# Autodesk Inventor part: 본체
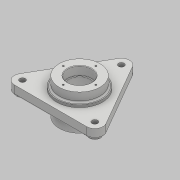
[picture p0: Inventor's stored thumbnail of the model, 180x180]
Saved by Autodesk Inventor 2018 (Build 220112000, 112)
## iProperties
Created: 2023-04
Part Number: 본체
Material: 일반
Document SubType Name: Modeling
Designer: home
Density: 1 g/cm^3
Appearance: 기본값
Author: home
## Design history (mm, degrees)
sketch "스케치1"
  geometry: L1 (-84.87, -33)-(-13.856, 90); L2 (-71.014, -57)-(71.014, -57); L3 (13.856, 90)-(84.87, -33); C1 r 5.5 at (0, 82); C2 r 5.5 at (71.014, -41); C3 r 5.5 at (-71.014, -41); A1 r 16 centre (-71.014, -41) between (-84.87, -33) and (-71.014, -57); A2 r 16 centre (71.014, -41) between (71.014, -57) and (84.87, -33); A3 r 16 centre (0, 82) between (13.856, 90) and (-13.856, 90); 1 further point
  constraints: 6 centre point, 6 end point, 6 point on circle, 3 coincident, 3 tangent, 1 horizontal
  dimensions: "d3" = 32 diameter of A1; "d4" = 32 diameter of A2; "d5" = 32 diameter of A3; "d6" = 11 diameter of C1; "d7" = 11 diameter of C2; "d8" = 11 diameter of C3
extrude "돌출1" new body sketch "스케치1" distance "d9" = 18; taper "d10" = 0 deg
sketch "스케치2"
  geometry: L1 (-71.014, -57)-(71.014, -57) reference; L2 (84.87, -33)-(13.856, 90) reference; L3 (-13.856, 90)-(-84.87, -33) reference; L4 (0, 82)-(0, 0); C1 r 5.5 at (-71.014, -41) reference; C2 r 5.5 at (71.014, -41) reference; C3 r 5.5 at (0, 82) reference; C4 r 5.5 at (0, 82) reference; C5 r 45 at (0, 0); A1 r 16 centre (-71.014, -41) between (-84.87, -33) and (-71.014, -57) reference; A2 r 16 centre (71.014, -41) between (71.014, -57) and (84.87, -33) reference; A3 r 16 centre (0, 82) between (13.856, 90) and (-13.856, 90) reference
  constraints: 2 end point, 1 centre point, 1 coincident, 1 vertical
  dimensions: "d11" = 90 diameter of C5
extrude "돌출2" join sketch "스케치2" distance "d12" = 5; taper "d13" = 0 deg
sketch "스케치3"
  geometry: C1 r 40 at (0, 0); 1 further point
  constraints: 1 centre point, 1 coincident
  dimensions: "d14" = 80 diameter of C1
extrude "돌출3" join sketch "스케치3" distance "d15" = 18; taper "d16" = 0 deg
sketch "스케치4"
  geometry: C1 r 40 at (0, 0); 1 further point
  constraints: 1 centre point, 1 coincident
  dimensions: "d18" = 80 diameter of C1
extrude "돌출4" join sketch "스케치4" distance "d19" = 29; taper "d20" = 0 deg
fillet "모깎기1" dims "d21" = 3
sketch "스케치5"
  geometry: L1 (13.856, 90)-(84.87, -33) reference; L2 (71.014, -57)-(-71.014, -57) reference; L3 (-84.87, -33)-(-13.856, 90) reference; C1 r 43 at (0, 0) reference; C2 r 5.5 at (71.014, -41) reference; C3 r 5.5 at (-71.014, -41) reference; C4 r 5.5 at (0, 82) reference; C5 r 5.5 at (0, 82) reference; C6 r 11 at (0, 82); C7 r 11 at (-71.014, -41); C8 r 5.5 at (71.014, -41) reference; C9 r 11 at (71.014, -41); A1 r 16 centre (71.014, -41) between (71.014, -57) and (84.87, -33) reference; A2 r 16 centre (-71.014, -41) between (-84.87, -33) and (-71.014, -57) reference; A3 r 16 centre (0, 82) between (13.856, 90) and (-13.856, 90) reference; 1 further point
  constraints: 3 centre point, 3 coincident
  dimensions: "d22" = 22 diameter of C6; "d23" = 22 diameter of C7; "d24" = 22 diameter of C9
extrude "돌출5" join sketch "스케치5" distance "d25" = 4; taper "d26" = 0 deg
fillet "모깎기2" dims "d27" = 3
fillet "모깎기3" dims "d28" = 3
sketch "스케치6"
  geometry: 5 further points
hole "구멍1" sketch "스케치6" at (0, 32), (-32, 0), (0, -32), (32, 0) diameter "d30" = 3.242; stored, may be unused: countersink angle "d34" = 90 deg, drill point angle "d36" = 118 deg; dims "d31" = 8, "d32" = 4, "d33" = 2, "d35" = 10
sketch "스케치7"
  geometry: C1 r 1.621 at (0, 32) reference; C2 r 1.621 at (-32, 0) reference; C3 r 1.621 at (0, -32) reference; C4 r 1.621 at (32, 0) reference; 5 further points
  constraints: 4 coincident
hole "구멍2" sketch "스케치7" at (0, 32), (-32, 0), (0, -32), (32, 0) diameter "d38" = 3.242; stored, may be unused: countersink angle "d42" = 90 deg, drill point angle "d44" = 118 deg; dims "d39" = 8, "d40" = 4, "d41" = 2, "d43" = 10
hole "구멍3" diameter "d47" = 42; stored, may be unused: countersink angle "d51" = 90 deg, drill point angle "d53" = 118 deg; dims "d45" = 10, "d46" = 10, "d48" = 8, "d49" = 47, "d50" = 17, "d52" = 80
hole "구멍4" diameter "d56" = 42; stored, may be unused: countersink angle "d60" = 90 deg, drill point angle "d62" = 118 deg; dims "d54" = 10, "d55" = 10, "d57" = 8, "d58" = 47, "d59" = 17, "d61" = 80
fillet "모깎기4" dims "d63" = 0.6
chamfer "모따기1" distance "d64" = 1; stored, may be unused: second distance "d65" = 2, angle "d66" = 45 deg
sketch "스케치8"
  geometry: L1 (0, 0)-(0, 60); 1 further point
  constraints: 2 end point, 1 coincident, 1 vertical, 1 other
  dimensions: "d67" = 60 distance of L1.start L1.end
feature "엠보싱1" sketch "스케치8" dims "d3" = 32, "d4" = 32, "d5" = 32, "d6" = 11, "d7" = 11, "d8" = 11, "d68" = 0.5, "d69" = 0
node "솔리드1"
node "투영된 루프1"
node "절단 모서리 투영1"
